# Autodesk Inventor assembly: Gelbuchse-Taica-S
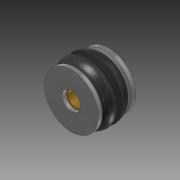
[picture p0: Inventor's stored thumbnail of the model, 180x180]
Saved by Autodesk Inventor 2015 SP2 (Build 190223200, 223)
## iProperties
Created: 2014-11
Part Number: Gelbuchse-Taica-S
Document SubType Name: Assembly
Designer: Hübner
Author: Hübner
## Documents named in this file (5)
- E:\Tigers SVN\mechanik\2016\Inventor\Kaufteile\Gelbuchse-Taica-S.iam
- E:\Tigers SVN\mechanik\2016\Inventor\Kaufteile\Gelbuchse-Taica-S-(A).ipt
- E:\Tigers SVN\mechanik\2016\Inventor\Kaufteile\Gelbuchse-Taica-S-(B).ipt
- E:\Tigers SVN\mechanik\2016\Inventor\Kaufteile\Gelbuchse-Taica-S-(C).ipt
- E:\Tigers SVN\mechanik\2016\Inventor\Inhaltscenter\de-DE\DIN 9021\DIN 9021 - 3,7.ipt
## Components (5 placed, 4 different names)
1. Gelbuchse-Taica-S-(A):1 — Passend:1, Passend:2, Einfügen:3
2. Gelbuchse-Taica-S-(B):1 — Passend:1, Passend:2
3. Gelbuchse-Taica-S-(C):1 — Einfügen:3
4. DIN 9021 3,7:1
5. DIN 9021 3,7:2
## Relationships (3: Mate 2, Insert 1)
- Passend:1 [Mate]: Gelbuchse-Taica-S-(A):1 ↔ Gelbuchse-Taica-S-(B):1
- Passend:2 [Mate]: Gelbuchse-Taica-S-(A):1 ↔ Gelbuchse-Taica-S-(B):1
- Einfügen:3 [Insert]: Gelbuchse-Taica-S-(A):1 ↔ Gelbuchse-Taica-S-(C):1
